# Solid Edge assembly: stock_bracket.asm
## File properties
Title: Solid Edge 20
Author: vicky raina
Template: Normal.asm
Last saved by: MYPC
Revision: 30
Application: Solid Edge
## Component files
adjusting_screw_guide.par
adjusting_nut_handle.par
stock_support_roller.par
Stock_support_base.par
thrust_bearing.par
adjusting_screw_nut.par
support_adjusting_screw.par
support_roller_bracket.par
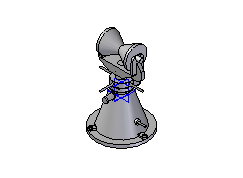
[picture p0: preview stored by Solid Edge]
